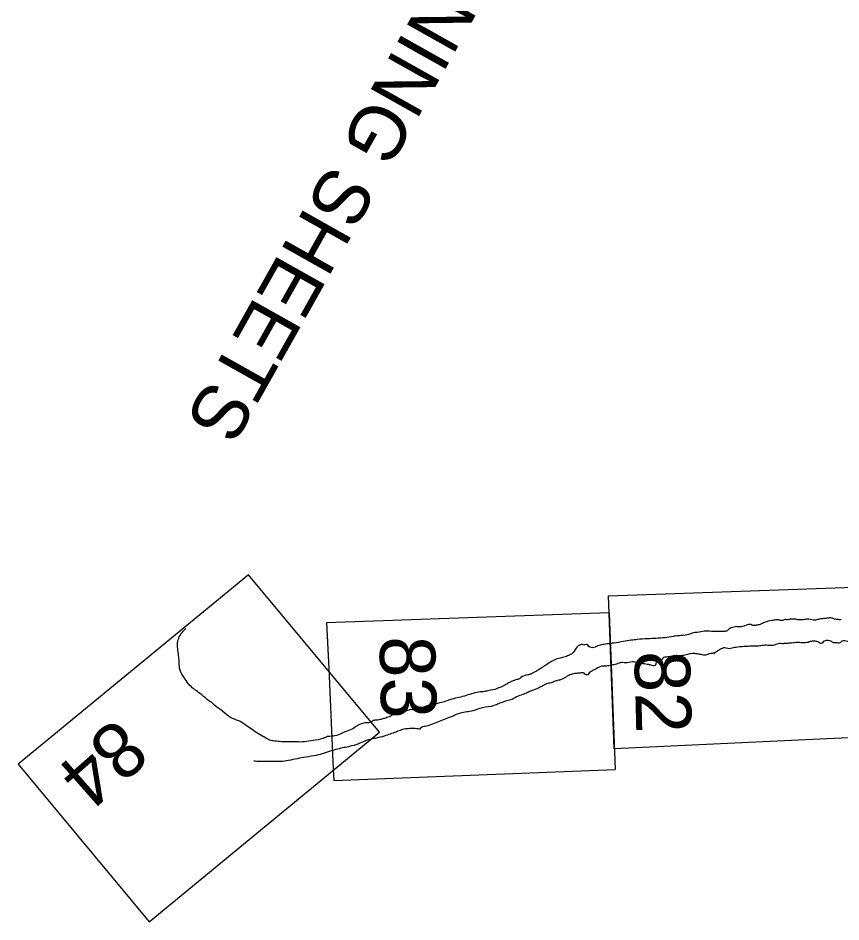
# Model space of a CAD drawing. Extents: x 3913936 to 3933962, y 195330 to 217741.
# Drawn here: x 3917304 to 3918173, y 205045 to 205998 of the extents above; entities that cross this region are included whole.
import ezdxf

# ---------------------------------------------------------------- set-up
doc = ezdxf.new("R2010")
doc.units = 0
doc.layers.add('V-ANNO-NPLT', color=7, linetype='Continuous')

msp = doc.modelspace()

# ---------------------------------------------------------------- linework, layer by layer
at = {"layer": 'V-ANNO-NPLT'}
for points in [[(3917547.58, 205411.32), (3917304.45, 205211.36), (3917442.7, 205045.11), (3917685.97, 205245.14)], [(3917685.97, 205245.14), (3917547.58, 205411.32)], [(3917933.63, 205227.81), (3917927.4, 205389.17), (3918226.36, 205399.46)], [(3917928.1, 205371.17), (3917630.08, 205360.38), (3917632.25, 205312.21)], [(3917928.1, 205371.17), (3917934.47, 205205.91)], [(3917632.25, 205312.21), (3917637.02, 205206.08)], [(3918232.91, 205241.81), (3917933.63, 205227.81)], [(3917637.02, 205206.08), (3917637.56, 205194.09), (3917934.47, 205205.91)]]:
    msp.add_lwpolyline(points, dxfattribs=at)
for points in [[(3918112.1, 205363.25), (3918110.55, 205362.98), (3918107.08, 205363.55), (3918103.58, 205363.56), (3918099.7, 205362.92), (3918092.11, 205360.94), (3918087.68, 205358.87), (3918083.33, 205357.92), (3918079.7, 205357.71), (3918077.61, 205358.64), (3918072.48, 205357.86), (3918067.87, 205356.48), (3918064.58, 205356.36), (3918063.15, 205356.44)], [(3918125.49, 205364.29), (3918122.33, 205364.31), (3918119.36, 205364.23), (3918115.73, 205363.82), (3918113.42, 205363.88), (3918112.1, 205363.25)], [(3918164.41, 205365.18), (3918163.08, 205365.6), (3918161.39, 205365.72), (3918157.29, 205365.2), (3918153.32, 205364.9), (3918149.09, 205364.17), (3918145.08, 205363.31), (3918138.93, 205364.29), (3918134.05, 205363.94), (3918130.08, 205363.64), (3918127.27, 205363.83), (3918125.49, 205364.29)], [(3918172.77, 205363.96), (3918171.3, 205363.82), (3918169.44, 205364), (3918166.88, 205364.29), (3918165.96, 205364.52), (3918164.41, 205365.18)], [(3917505.77, 205278.26), (3917498.35, 205284.45), (3917492.16, 205289.13), (3917486.95, 205293.23), (3917482.9, 205297.97), (3917478.55, 205304.46), (3917474.93, 205312.62), (3917474.5, 205319.96), (3917473.89, 205326.09), (3917472.96, 205333.46), (3917472.86, 205339.56), (3917474.58, 205345.63), (3917478.63, 205351.66), (3917481.59, 205354.49)], [(3918053.27, 205352.54), (3918052.61, 205352.14), (3918049.51, 205351.33), (3918045.45, 205351.38), (3918041.6, 205351.3), (3918036.19, 205351.55), (3918028.41, 205351.73), (3918021.21, 205350.41), (3918018.49, 205350.25), (3918012.84, 205348.6), (3918004.04, 205347.05), (3918001.32, 205346.89), (3917997.91, 205346.56), (3917995.62, 205346.14)], [(3918063.15, 205356.44), (3918061.01, 205356.46), (3918058.23, 205355.65), (3918055.72, 205354.59), (3918054.15, 205353.47), (3918053.27, 205352.54)], [(3917995.62, 205346.14), (3917986.95, 205344.81), (3917977.75, 205344.07), (3917968.46, 205343.68), (3917957.79, 205342.93), (3917951.53, 205342.22), (3917942.86, 205340.88), (3917933.37, 205339.15), (3917929.05, 205338.76), (3917922.88, 205337.71), (3917917.62, 205336.71), (3917912.15, 205334.37), (3917906.82, 205335.74), (3917905.24, 205337.54), (3917902.87, 205337.48), (3917901.49, 205337.12)], [(3918144.48, 205341.38), (3918140.65, 205340.8), (3918138.11, 205339.96), (3918132.54, 205339.43), (3918128.04, 205339.73), (3918122.25, 205339.33), (3918118.84, 205338.99), (3918114.65, 205338.82), (3918110.68, 205338.53), (3918108.08, 205338.59), (3918105.11, 205338), (3918101.4, 205336.67), (3918098.81, 205336.73), (3918097.34, 205336.71)], [(3918229.77, 205337.45), (3918226.77, 205338.91), (3918224.96, 205338.81), (3918219.46, 205339.4), (3918214.78, 205340.4), (3918210.2, 205341.04), (3918205.88, 205340.65), (3918202.72, 205340.75), (3918196.84, 205340.7), (3918191.62, 205340.26), (3918188.21, 205339.92), (3918184.62, 205340.28), (3918181.02, 205340.63), (3918175.44, 205341.57), (3918172.99, 205340.38), (3918171.92, 205339.55), (3918167.72, 205339.38), (3918164.91, 205339.57), (3918162.3, 205341.1), (3918159.31, 205341.98), (3918155.08, 205341.24), (3918153.16, 205339.46), (3918152.08, 205338.62), (3918149.35, 205339.94), (3918147.48, 205340.74), (3918145.7, 205341.2), (3918144.36, 205341.4)], [(3917901.49, 205337.12), (3917898.76, 205337.69), (3917896.91, 205337.03), (3917894.42, 205335.28), (3917890.29, 205329.23), (3917887.55, 205327.05), (3917883.24, 205325.19), (3917877.73, 205323.75), (3917872.43, 205322.19), (3917869.16, 205320.6), (3917864.47, 205318.1), (3917860.44, 205315.2), (3917857.39, 205313.49), (3917853.49, 205310.82), (3917849.15, 205308.4), (3917845.41, 205306.51), (3917842.3, 205305.7), (3917835.11, 205302.91), (3917833.44, 205301.55), (3917829.87, 205300.44), (3917825.82, 205299.02), (3917822.08, 205297.12), (3917818.08, 205294.8), (3917815.16, 205293.3), (3917812.83, 205292.33), (3917810.17, 205291.26), (3917809.35, 205290.87)], [(3918097.34, 205336.71), (3918091.07, 205336.74), (3918085.72, 205336.08), (3918079.5, 205335.94), (3918073.15, 205335.57), (3918063.73, 205334.96), (3918058, 205333.66), (3918054.8, 205333.19), (3918048.87, 205334.04), (3918045.73, 205332.67), (3918041.26, 205330.04), (3918040.32, 205329.42), (3918038.52, 205327.85)], [(3917980.37, 205320.64), (3917977.63, 205318.45), (3917977.3, 205316.89), (3917976.41, 205315.37), (3917974.6, 205315.27), (3917971.6, 205316.15), (3917968.14, 205316.72), (3917962.55, 205317.66), (3917957.31, 205318.69), (3917952.38, 205319.25), (3917945.65, 205318.23), (3917942.4, 205318.67), (3917937.36, 205317.55), (3917934.47, 205316.61), (3917929.21, 205315.61), (3917924.29, 205314.7), (3917920.23, 205314.74), (3917912.4, 205310.87), (3917909.13, 205309.28), (3917905.62, 205305.79)], [(3918039.18, 205328.43), (3918036.92, 205328.36), (3918034.07, 205327.98), (3918030.02, 205326.56), (3918025.3, 205326.99), (3918021.06, 205327.73), (3918016, 205328.07), (3918010.74, 205327.07), (3918005.13, 205325.97), (3918001.15, 205325.68), (3917994.11, 205325.13), (3917988.76, 205324.48), (3917984.84, 205323.27), (3917983.22, 205321.01), (3917980.37, 205320.64)], [(3917905.64, 205305.81), (3917904.89, 205305.78), (3917903.42, 205305.77), (3917901.72, 205307.35), (3917897.44, 205307.53), (3917893.12, 205307.14), (3917888.07, 205306.01), (3917883.3, 205303.85), (3917878.01, 205300.82), (3917873.53, 205299.65), (3917869.14, 205298.14), (3917864.53, 205296.76), (3917860.61, 205295.55), (3917857.08, 205293.53), (3917852.53, 205291.24), (3917845.34, 205288.45), (3917840.91, 205286.37), (3917837.08, 205284.83), (3917830.49, 205282.56), (3917825.68, 205279.83), (3917820.16, 205278.4), (3917814.13, 205276.1), (3917811.59, 205275.25)], [(3917809.35, 205290.87), (3917801.55, 205289.02), (3917796.63, 205288.11), (3917790.37, 205287.4), (3917775.41, 205283.32), (3917760.24, 205279.38), (3917748.13, 205275.67), (3917738.99, 205274.03), (3917731.58, 205271.37), (3917724.77, 205269.23), (3917718.21, 205268.99)], [(3917563.5, 205240.48), (3917549.64, 205249.12), (3917537.28, 205257.16), (3917528.57, 205260.69), (3917520.62, 205267.06), (3917512.19, 205273.32), (3917508.66, 205276.7), (3917505.77, 205278.26)], [(3917811.63, 205275.26), (3917806.6, 205273.21), (3917794.13, 205270.89), (3917784.44, 205267.82), (3917771.28, 205265.31), (3917759.44, 205260.58), (3917745.41, 205255.08), (3917737.88, 205252.2), (3917732.83, 205251.08), (3917728.37, 205248.44), (3917728.31, 205248.04)], [(3917718.21, 205268.99), (3917715.24, 205268.08), (3917712.3, 205266.54), (3917709.71, 205265.61), (3917706.7, 205265.34), (3917703.86, 205265.37), (3917698.82, 205263.03), (3917695.88, 205261.5), (3917691.19, 205259.76), (3917687.34, 205258.76), (3917682.7, 205257.81), (3917679.21, 205257.41), (3917676.09, 205255.57), (3917672.59, 205255.18), (3917669.1, 205254.78), (3917664.89, 205253.18), (3917660.81, 205251.09), (3917659.28, 205249.67)], [(3917659.28, 205249.67), (3917652.28, 205246.69), (3917646.32, 205244.15), (3917638.81, 205241.2), (3917631.05, 205240.51), (3917626.25, 205238.6), (3917615.74, 205236.36), (3917606.81, 205235.03), (3917598.07, 205234.91), (3917588.93, 205235.01), (3917580.42, 205235.28), (3917573.76, 205236.03), (3917569.17, 205237.15), (3917564.47, 205239.9), (3917563.5, 205240.48)], [(3917728.33, 205248.28), (3917721.71, 205249.2), (3917717.92, 205248.98), (3917711.89, 205248.44), (3917703.17, 205245.4), (3917690.9, 205241.18), (3917681.27, 205238.68), (3917675.68, 205237.48), (3917665.16, 205233.46), (3917656.62, 205230.72), (3917643.49, 205227.82), (3917635.79, 205225.81)], [(3917635.79, 205225.81), (3917619.13, 205220.71), (3917608.29, 205218.92), (3917589.92, 205215.42), (3917581.48, 205214.25), (3917573.28, 205214.18), (3917559.88, 205214.29), (3917553.12, 205214.58)]]:
    msp.add_spline(points, degree=3, dxfattribs=at)

# ---------------------------------------------------------------- texts
for s, height, rotation, p in [('INDEX TO ADJOINING SHEETS', 58.33, 240.65792, (3918043.15, 206575.34)), ('83', 58.5, 271.36981, (3917685.79, 205345.99)), ('82', 58.5, 271.36981, (3917954.77, 205330.43)), ('84', 58.5, 221.3698, (3917407.95, 205262.16))]:
    msp.add_text(s, height=height, rotation=rotation, dxfattribs=at).set_placement(p)

doc.saveas('drawing.dxf')
